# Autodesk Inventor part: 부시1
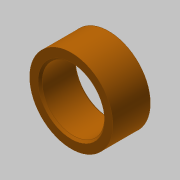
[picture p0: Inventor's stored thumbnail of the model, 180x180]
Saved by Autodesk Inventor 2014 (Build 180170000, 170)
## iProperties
Created: 2016-08
Part Number: 부시1
Material: 강철, 탄소
Document SubType Name: Modeling
Designer: mduedu
Density: 7.87 g/cm^3
Appearance: Orange
Author: mduedu
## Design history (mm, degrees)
sketch "스케치1"
  geometry: C1 r 7.5 at (0, 0); C2 r 10 at (0, 0); 1 further point
  constraints: 2 centre point, 2 coincident
  dimensions: "d0" = 15 diameter of C1; "d1" = 20 diameter of C2
extrude "돌출1" new body sketch "스케치1" stored distance "d2" = 9; taper "d3" = 0 deg
chamfer "모따기1" distance "d4" = 0.5; stored, may be unused: second distance "d5" = 2, angle "d6" = 45 deg
node "솔리드1"
